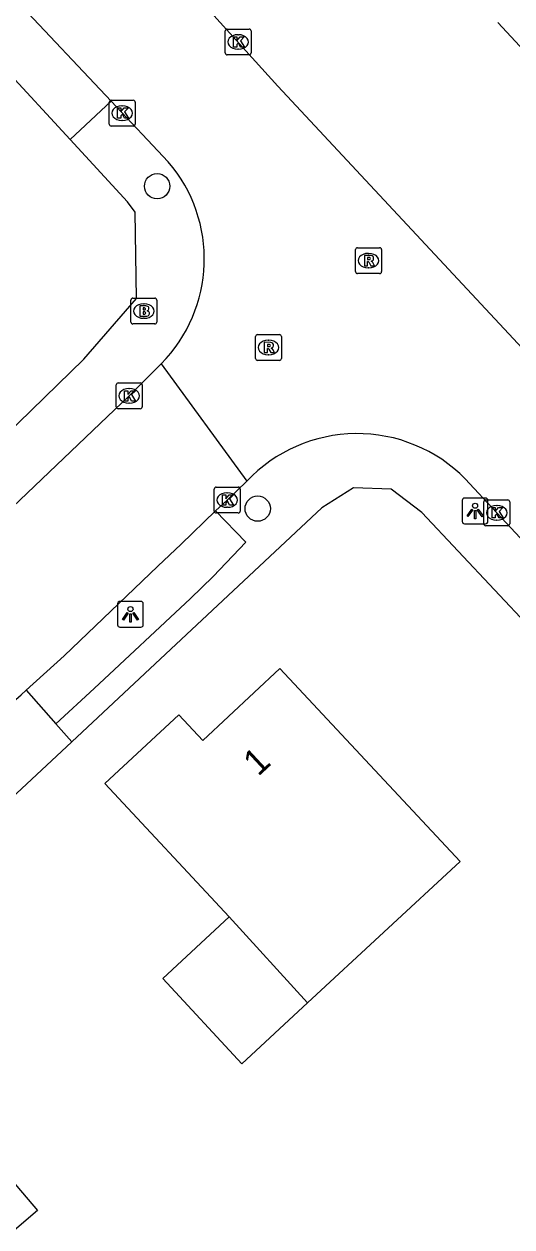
# Model space of a CAD drawing. Extents: x 162675 to 163482, y 379761 to 381227.
# Drawn here: x 163281.52 to 163300.37, y 380931.1 to 380977.63 of the extents above; entities that cross this region are included whole.
import ezdxf

# ---------------------------------------------------------------- set-up
doc = ezdxf.new("R2010")
doc.units = 0
for name, color, linetype in [('IMGEO_Berm_groen', 7, 'Continuous'), ('IMGEO_Boom', 7, 'Continuous'), ('IMGEO_Brandkraan', 7, 'Continuous'), ('IMGEO_Kolk', 7, 'Continuous'), ('IMGEO_Lichtpunt', 7, 'Continuous'), ('IMGEO_Pand', 7, 'Continuous'), ('IMGEO_Pand_nummerreeks', 7, 'Continuous'), ('IMGEO_Rijbaan_lokaal_gesloten', 7, 'Continuous'), ('IMGEO_Rioolput', 7, 'Continuous'), ('IMGEO_Voetpad_open', 7, 'Continuous')]:
    doc.layers.add(name, color=color, linetype=linetype)

msp = doc.modelspace()

# ---------------------------------------------------------------- linework, layer by layer
at = {"layer": 'IMGEO_Berm_groen'}
for points in [[(163283.301, 380973.164), (163270.341, 380987.244), (163262.225, 380995.879)], [(163284.882, 380974.654), (163283.301, 380973.164)], [(163245.355, 380932.175), (163256.849, 380940.728), (163265.587, 380947.667), (163275.197, 380956.267), (163283.823, 380964.675), (163285.861, 380967.011), (163285.811, 380970.355), (163285.512, 380970.762), (163283.301, 380973.164)], [(163317.332, 380927.055), (163320.579, 380929.984), (163321.057, 380930.657), (163321.299, 380931.564), (163321.184, 380932.515), (163320.761, 380933.306), (163296.884, 380958.739), (163295.699, 380959.641), (163294.252, 380959.688), (163293.024, 380958.913), (163283.361, 380949.868)], [(163288.921, 380958.797), (163290.086, 380957.585), (163288.827, 380956.259), (163287.951, 380955.412), (163284.229, 380951.924), (163282.745, 380950.566)]]:
    msp.add_lwpolyline(points, dxfattribs=at)
at = {"layer": 'IMGEO_Boom'}
for centre in [(163286.66, 380971.36), (163290.547, 380958.887)]:
    msp.add_circle(centre, 0.489, dxfattribs=at)
at = {"layer": 'IMGEO_Brandkraan'}
for p, q in [((163285.644, 380966.104), (163285.644, 380966.956)), ((163285.719, 380967.03), (163286.571, 380967.03)), ((163286.132, 380966.81), (163286.157, 380966.81)), ((163286.645, 380966.956), (163286.645, 380966.104)), ((163286.155, 380966.25), (163286.13, 380966.25)), ((163286.571, 380966.03), (163285.719, 380966.03))]:
    msp.add_line(p, q, dxfattribs=at)
for points in [[(163285.644, 380966.104), (163285.644, 380966.956)], [(163285.719, 380967.03), (163286.571, 380967.03)], [(163285.992, 380966.73), (163285.992, 380966.33), (163286.205, 380966.33)], [(163286.223, 380966.73), (163285.992, 380966.73)], [(163286.171, 380966.649), (163286.117, 380966.649), (163286.117, 380966.573)], [(163286.645, 380966.956), (163286.645, 380966.104)], [(163286.117, 380966.573), (163286.17, 380966.573)], [(163286.179, 380966.497), (163286.117, 380966.497), (163286.117, 380966.416)], [(163286.117, 380966.416), (163286.179, 380966.416)], [(163286.571, 380966.03), (163285.719, 380966.03)]]:
    msp.add_lwpolyline(points, dxfattribs=at)
for centre, radius, start, end in [((163285.721, 380966.954), 0.0765, 91.552, 178.448), ((163285.721, 380966.954), 0.0765, 91.552, 178.448), ((163286.172, 380966.611), 0.0379, 267.8285, 90.9355), ((163286.227, 380966.585), 0.145, 59.4692, 91.5367), ((163286.252, 380966.632), 0.0922, 285.5137, 58.1501), ((163286.569, 380966.954), 0.0765, 1.552, 88.448), ((163286.569, 380966.954), 0.0765, 1.552, 88.448), ((163286.18, 380966.456), 0.0404, 269.8759, 90.5077), ((163286.211, 380966.581), 0.251, 268.6676, 293.5347), ((163286.257, 380966.44), 0.105, 301.3115, 78.989), ((163285.721, 380966.106), 0.0765, 181.552, 268.448), ((163285.721, 380966.106), 0.0765, 181.552, 268.448), ((163286.569, 380966.106), 0.0765, 271.552, 358.448), ((163286.569, 380966.106), 0.0765, 271.552, 358.448)]:
    msp.add_arc(centre, radius, start, end, dxfattribs=at)
for centre, major_axis, ratio, start_param, end_param in [((163286.131, 380966.53), (-0.387, 0.002), 0.722429, 4.712389, 7.853982), ((163286.156, 380966.53), (-0.39, 0.002), 0.717154, 1.570796, 4.712389)]:
    msp.add_ellipse(centre, major_axis=major_axis, ratio=ratio, start_param=start_param, end_param=end_param, dxfattribs=at)
at = {"layer": 'IMGEO_Kolk'}
for p, q in [((163289.291, 380976.516), (163289.291, 380977.368)), ((163289.366, 380977.442), (163290.218, 380977.442)), ((163290.292, 380977.368), (163290.292, 380976.516)), ((163289.779, 380977.222), (163289.804, 380977.222)), ((163290.218, 380976.442), (163289.366, 380976.442)), ((163289.802, 380976.662), (163289.777, 380976.662)), ((163284.811, 380973.763), (163284.811, 380974.615)), ((163284.886, 380974.689), (163285.738, 380974.689)), ((163285.812, 380974.615), (163285.812, 380973.763)), ((163285.299, 380974.469), (163285.324, 380974.469)), ((163285.738, 380973.689), (163284.886, 380973.689)), ((163285.322, 380973.909), (163285.297, 380973.909)), ((163285.083, 380962.824), (163285.083, 380963.676)), ((163285.158, 380963.75), (163286.01, 380963.75)), ((163285.571, 380963.53), (163285.596, 380963.53)), ((163286.084, 380963.676), (163286.084, 380962.824)), ((163285.594, 380962.97), (163285.569, 380962.97)), ((163286.01, 380962.75), (163285.158, 380962.75)), ((163288.945, 380959.718), (163289.797, 380959.718)), ((163288.87, 380958.792), (163288.87, 380959.644)), ((163289.358, 380959.498), (163289.383, 380959.498)), ((163289.871, 380959.644), (163289.871, 380958.792)), ((163299.359, 380959.226), (163300.211, 380959.226)), ((163289.381, 380958.938), (163289.356, 380958.938)), ((163299.284, 380958.3), (163299.284, 380959.152)), ((163299.772, 380959.006), (163299.797, 380959.006)), ((163300.285, 380959.152), (163300.285, 380958.3)), ((163289.797, 380958.718), (163288.945, 380958.718)), ((163299.795, 380958.446), (163299.77, 380958.446)), ((163300.211, 380958.226), (163299.359, 380958.226))]:
    msp.add_line(p, q, dxfattribs=at)
for points in [[(163289.291, 380976.516), (163289.291, 380977.368)], [(163289.366, 380977.442), (163290.218, 380977.442)], [(163290.292, 380977.368), (163290.292, 380976.516)], [(163289.612, 380977.142), (163289.735, 380977.142), (163289.735, 380976.991), (163289.865, 380977.142), (163290.029, 380977.142), (163289.883, 380976.991), (163290.036, 380976.742), (163289.884, 380976.742), (163289.799, 380976.906), (163289.735, 380976.839), (163289.735, 380976.742), (163289.612, 380976.742), (163289.612, 380977.142)], [(163290.218, 380976.442), (163289.366, 380976.442)], [(163284.811, 380973.763), (163284.811, 380974.615)], [(163284.886, 380974.689), (163285.738, 380974.689)], [(163285.812, 380974.615), (163285.812, 380973.763)], [(163285.132, 380974.389), (163285.255, 380974.389), (163285.255, 380974.238), (163285.385, 380974.389), (163285.549, 380974.389), (163285.403, 380974.238), (163285.556, 380973.989), (163285.404, 380973.989), (163285.319, 380974.153), (163285.255, 380974.086), (163285.255, 380973.989), (163285.132, 380973.989), (163285.132, 380974.389)], [(163285.738, 380973.689), (163284.886, 380973.689)], [(163285.083, 380962.824), (163285.083, 380963.676)], [(163285.158, 380963.75), (163286.01, 380963.75)], [(163285.404, 380963.45), (163285.527, 380963.45), (163285.527, 380963.299), (163285.657, 380963.45), (163285.821, 380963.45), (163285.675, 380963.299), (163285.828, 380963.05), (163285.676, 380963.05), (163285.591, 380963.214), (163285.527, 380963.147), (163285.527, 380963.05), (163285.404, 380963.05), (163285.404, 380963.45)], [(163286.084, 380963.676), (163286.084, 380962.824)], [(163286.01, 380962.75), (163285.158, 380962.75)], [(163288.945, 380959.718), (163289.797, 380959.718)], [(163288.87, 380958.792), (163288.87, 380959.644)], [(163289.191, 380959.418), (163289.314, 380959.418), (163289.314, 380959.267), (163289.444, 380959.418), (163289.608, 380959.418), (163289.462, 380959.267), (163289.615, 380959.018), (163289.463, 380959.018), (163289.378, 380959.182), (163289.314, 380959.115), (163289.314, 380959.018), (163289.191, 380959.018), (163289.191, 380959.418)], [(163289.871, 380959.644), (163289.871, 380958.792)], [(163299.359, 380959.226), (163300.211, 380959.226)], [(163299.284, 380958.3), (163299.284, 380959.152)], [(163299.605, 380958.926), (163299.728, 380958.926), (163299.728, 380958.775), (163299.858, 380958.926), (163300.022, 380958.926), (163299.876, 380958.775), (163300.029, 380958.526), (163299.877, 380958.526), (163299.792, 380958.69), (163299.728, 380958.623), (163299.728, 380958.526), (163299.605, 380958.526), (163299.605, 380958.926)], [(163300.285, 380959.152), (163300.285, 380958.3)], [(163289.797, 380958.718), (163288.945, 380958.718)], [(163300.211, 380958.226), (163299.359, 380958.226)]]:
    msp.add_lwpolyline(points, dxfattribs=at)
for centre, start, end in [((163289.368, 380977.366), 91.552, 178.448), ((163289.368, 380977.366), 91.552, 178.448), ((163290.216, 380977.366), 1.552, 88.448), ((163290.216, 380977.366), 1.552, 88.448), ((163289.368, 380976.518), 181.552, 268.448), ((163289.368, 380976.518), 181.552, 268.448), ((163290.216, 380976.518), 271.552, 358.448), ((163290.216, 380976.518), 271.552, 358.448), ((163284.888, 380974.613), 91.552, 178.448), ((163284.888, 380974.613), 91.552, 178.448), ((163285.736, 380974.613), 1.552, 88.448), ((163285.736, 380974.613), 1.552, 88.448), ((163284.888, 380973.765), 181.552, 268.448), ((163284.888, 380973.765), 181.552, 268.448), ((163285.736, 380973.765), 271.552, 358.448), ((163285.736, 380973.765), 271.552, 358.448), ((163285.16, 380963.674), 91.552, 178.448), ((163285.16, 380963.674), 91.552, 178.448), ((163286.008, 380963.674), 1.552, 88.448), ((163286.008, 380963.674), 1.552, 88.448), ((163285.16, 380962.826), 181.552, 268.448), ((163285.16, 380962.826), 181.552, 268.448), ((163286.008, 380962.826), 271.552, 358.448), ((163286.008, 380962.826), 271.552, 358.448), ((163288.947, 380959.642), 91.552, 178.448), ((163288.947, 380959.642), 91.552, 178.448), ((163289.795, 380959.642), 1.552, 88.448), ((163289.795, 380959.642), 1.552, 88.448), ((163299.361, 380959.15), 91.552, 178.448), ((163299.361, 380959.15), 91.552, 178.448), ((163300.209, 380959.15), 1.552, 88.448), ((163300.209, 380959.15), 1.552, 88.448), ((163288.947, 380958.794), 181.552, 268.448), ((163288.947, 380958.794), 181.552, 268.448), ((163289.795, 380958.794), 271.552, 358.448), ((163289.795, 380958.794), 271.552, 358.448), ((163299.361, 380958.302), 181.552, 268.448), ((163299.361, 380958.302), 181.552, 268.448), ((163300.209, 380958.302), 271.552, 358.448), ((163300.209, 380958.302), 271.552, 358.448)]:
    msp.add_arc(centre, 0.0765, start, end, dxfattribs=at)
for centre, major_axis, ratio, start_param, end_param in [((163289.778, 380976.942), (-0.387, 0.002), 0.722429, 4.712389, 7.853982), ((163289.803, 380976.942), (-0.39, 0.002), 0.717154, 1.570796, 4.712389), ((163285.298, 380974.189), (-0.387, 0.002), 0.722429, 4.712389, 7.853982), ((163285.323, 380974.189), (-0.39, 0.002), 0.717154, 1.570796, 4.712389), ((163285.57, 380963.25), (-0.387, 0.002), 0.722429, 4.712389, 7.853982), ((163285.595, 380963.25), (-0.39, 0.002), 0.717154, 1.570796, 4.712389), ((163289.357, 380959.218), (-0.387, 0.002), 0.722429, 4.712389, 7.853982), ((163289.382, 380959.218), (-0.39, 0.002), 0.717154, 1.570796, 4.712389), ((163299.771, 380958.726), (-0.387, 0.002), 0.722429, 4.712389, 7.853982), ((163299.796, 380958.726), (-0.39, 0.002), 0.717154, 1.570796, 4.712389)]:
    msp.add_ellipse(centre, major_axis=major_axis, ratio=ratio, start_param=start_param, end_param=end_param, dxfattribs=at)
at = {"layer": 'IMGEO_Lichtpunt'}
for p, q in [((163298.449, 380959.202), (163298.449, 380958.395)), ((163298.449, 380959.202), (163298.449, 380958.395)), ((163299.351, 380959.297), (163298.543, 380959.297)), ((163299.351, 380959.297), (163298.543, 380959.297)), ((163299.445, 380958.395), (163299.445, 380959.202)), ((163299.445, 380958.395), (163299.445, 380959.202)), ((163298.543, 380958.301), (163299.351, 380958.301)), ((163298.543, 380958.301), (163299.351, 380958.301)), ((163285.13, 380955.202), (163285.13, 380954.395)), ((163285.13, 380955.202), (163285.13, 380954.395)), ((163286.032, 380955.297), (163285.224, 380955.297)), ((163286.032, 380955.297), (163285.224, 380955.297)), ((163286.126, 380954.395), (163286.126, 380955.202)), ((163286.126, 380954.395), (163286.126, 380955.202)), ((163285.224, 380954.301), (163286.032, 380954.301)), ((163285.224, 380954.301), (163286.032, 380954.301))]:
    msp.add_line(p, q, dxfattribs=at)
for points in [[(163298.823, 380958.866), (163298.862, 380958.838), (163298.674, 380958.576), (163298.636, 380958.603), (163298.823, 380958.866)], [(163298.925, 380958.818), (163298.972, 380958.818), (163298.972, 380958.496), (163298.925, 380958.496), (163298.925, 380958.818)], [(163299.035, 380958.838), (163299.073, 380958.865), (163299.26, 380958.603), (163299.221, 380958.575), (163299.035, 380958.838)], [(163285.504, 380954.866), (163285.543, 380954.838), (163285.355, 380954.576), (163285.317, 380954.603), (163285.504, 380954.866)], [(163285.606, 380954.818), (163285.653, 380954.818), (163285.653, 380954.496), (163285.606, 380954.496), (163285.606, 380954.818)], [(163285.716, 380954.838), (163285.754, 380954.865), (163285.941, 380954.603), (163285.902, 380954.575), (163285.716, 380954.838)]]:
    msp.add_lwpolyline(points, dxfattribs=at)
for centre in [(163298.948, 380959), (163285.629, 380955)]:
    msp.add_circle(centre, 0.0994, dxfattribs=at)
for centre, start, end in [((163298.543, 380959.202), 90, 180), ((163298.543, 380959.202), 90, 180), ((163299.351, 380959.202), 0, 90), ((163299.351, 380959.202), 0, 90), ((163298.543, 380958.395), 180, 270), ((163298.543, 380958.395), 180, 270), ((163299.351, 380958.395), 270, 0), ((163299.351, 380958.395), 270, 360), ((163285.224, 380955.202), 90, 180), ((163285.224, 380955.202), 90, 180), ((163286.032, 380955.202), 0, 90), ((163286.032, 380955.202), 0, 90), ((163285.224, 380954.395), 180, 270), ((163285.224, 380954.395), 180, 270), ((163286.032, 380954.395), 270, 0), ((163286.032, 380954.395), 270, 360)]:
    msp.add_arc(centre, 0.0946, start, end, dxfattribs=at)
at = {"layer": 'IMGEO_Pand'}
for points in [[(163299.824, 380977.698), (163303.91, 380973.295)], [(163292.474, 380939.76), (163298.376, 380945.238), (163291.404, 380952.706), (163288.421, 380949.921), (163287.494, 380950.905), (163284.644, 380948.251), (163289.446, 380943.092)], [(163289.446, 380943.092), (163286.877, 380940.71), (163289.935, 380937.403), (163292.474, 380939.76)], [(163289.446, 380943.092), (163292.474, 380939.76)], [(163272.637, 380935.682), (163276.199, 380938.643), (163276.806, 380937.922), (163277.935, 380938.883), (163280.268, 380936.141), (163279.118, 380935.162), (163282.041, 380931.727), (163278.606, 380928.803), (163279.89, 380927.294), (163280.071, 380927.082), (163274.67, 380922.486), (163270.866, 380926.955), (163269.468, 380928.597), (163272.133, 380930.865), (163270.614, 380932.649), (163273.28, 380934.918), (163272.637, 380935.682)]]:
    msp.add_lwpolyline(points, dxfattribs=at)
at = {"layer": 'IMGEO_Rijbaan_lokaal_gesloten'}
for points in [[(163262.994, 380997.873), (163284.882, 380974.654)], [(163308.847, 380956.416), (163303.455, 380962.21), (163291.33, 380975.235), (163272.753, 380995.764)], [(163284.882, 380974.654), (163287.093, 380972.307)], [(163286.815, 380964.484), (163285.584, 380963.25), (163280.503, 380958.42)], [(163286.815, 380964.484), (163290.124, 380959.948)], [(163288.921, 380958.797), (163289.371, 380959.218), (163290.124, 380959.948)], [(163298.568, 380960.041), (163299.785, 380958.726), (163311.732, 380945.919), (163320.596, 380936.397), (163322.059, 380934.813)], [(163281.602, 380951.861), (163283.071, 380953.186), (163286.688, 380956.667), (163287.589, 380957.512), (163288.921, 380958.797)]]:
    msp.add_lwpolyline(points, dxfattribs=at)
for centre, radius, start, end in [((163282.7, 380968.547), 5.782, 315.3653, 40.5643), ((163294.391, 380955.922), 5.867, 44.5995, 136.6625), ((162724.481, 381570.415), 832.462, 311.710307, 312.008798)]:
    msp.add_arc(centre, radius, start, end, dxfattribs=at)
at = {"layer": 'IMGEO_Rioolput'}
for p, q in [((163294.407, 380968.981), (163295.259, 380968.981)), ((163294.332, 380968.055), (163294.332, 380968.907)), ((163294.82, 380968.761), (163294.845, 380968.761)), ((163295.333, 380968.907), (163295.333, 380968.055)), ((163294.843, 380968.201), (163294.818, 380968.201)), ((163295.259, 380967.981), (163294.407, 380967.981)), ((163290.463, 380964.695), (163290.463, 380965.547)), ((163290.538, 380965.621), (163291.39, 380965.621)), ((163290.951, 380965.401), (163290.976, 380965.401)), ((163291.464, 380965.547), (163291.464, 380964.695)), ((163290.974, 380964.841), (163290.949, 380964.841)), ((163291.39, 380964.621), (163290.538, 380964.621))]:
    msp.add_line(p, q, dxfattribs=at)
for points in [[(163294.407, 380968.981), (163295.259, 380968.981)], [(163294.332, 380968.055), (163294.332, 380968.907)], [(163294.921, 380968.679), (163294.669, 380968.681), (163294.669, 380968.281)], [(163294.847, 380968.6), (163294.793, 380968.6), (163294.793, 380968.519)], [(163294.793, 380968.519), (163294.845, 380968.519)], [(163295.333, 380968.907), (163295.333, 380968.055)], [(163294.669, 380968.281), (163294.793, 380968.281), (163294.793, 380968.443), (163294.804, 380968.443)], [(163294.851, 380968.414), (163294.922, 380968.281), (163295.062, 380968.281), (163294.997, 380968.407)], [(163295.259, 380967.981), (163294.407, 380967.981)], [(163290.463, 380964.695), (163290.463, 380965.547)], [(163290.538, 380965.621), (163291.39, 380965.621)], [(163291.052, 380965.319), (163290.8, 380965.321), (163290.8, 380964.921)], [(163290.978, 380965.24), (163290.924, 380965.24), (163290.924, 380965.159)], [(163291.464, 380965.547), (163291.464, 380964.695)], [(163290.8, 380964.921), (163290.924, 380964.921), (163290.924, 380965.083), (163290.935, 380965.083)], [(163290.924, 380965.159), (163290.976, 380965.159)], [(163290.982, 380965.054), (163291.053, 380964.921), (163291.193, 380964.921), (163291.128, 380965.047)], [(163291.39, 380964.621), (163290.538, 380964.621)]]:
    msp.add_lwpolyline(points, dxfattribs=at)
for centre, radius, start, end in [((163294.409, 380968.905), 0.0765, 91.552, 178.448), ((163294.409, 380968.905), 0.0765, 91.552, 178.448), ((163295.257, 380968.905), 0.0765, 1.552, 88.448), ((163295.257, 380968.905), 0.0765, 1.552, 88.448), ((163294.829, 380968.708), 0.19, 274.7715, 282.9687), ((163294.853, 380968.504), 0.0964, 77.0061, 93.1865), ((163294.867, 380968.561), 0.0378, 276.6634, 79.6772), ((163294.92, 380968.569), 0.109, 350.3612, 89.416), ((163294.918, 380968.569), 0.112, 277.5842, 350.9817), ((163294.409, 380968.057), 0.0765, 181.552, 268.448), ((163294.409, 380968.057), 0.0765, 181.552, 268.448), ((163294.803, 380968.39), 0.0533, 26.0293, 88.6989), ((163294.902, 380968.354), 0.108, 29.5134, 73.7905), ((163295.257, 380968.057), 0.0765, 271.552, 358.448), ((163295.257, 380968.057), 0.0765, 271.552, 358.448), ((163290.54, 380965.545), 0.0765, 91.552, 178.448), ((163290.54, 380965.545), 0.0765, 91.552, 178.448), ((163290.984, 380965.144), 0.0964, 77.0061, 93.1865), ((163290.998, 380965.201), 0.0378, 276.6634, 79.6772), ((163291.051, 380965.209), 0.109, 350.3612, 89.416), ((163291.388, 380965.545), 0.0765, 1.552, 88.448), ((163291.388, 380965.545), 0.0765, 1.552, 88.448), ((163290.934, 380965.03), 0.0533, 26.0293, 88.6989), ((163290.96, 380965.348), 0.19, 274.7715, 282.9687), ((163291.049, 380965.209), 0.112, 277.5842, 350.9817), ((163291.033, 380964.994), 0.108, 29.5134, 73.7905), ((163290.54, 380964.697), 0.0765, 181.552, 268.448), ((163290.54, 380964.697), 0.0765, 181.552, 268.448), ((163291.388, 380964.697), 0.0765, 271.552, 358.448), ((163291.388, 380964.697), 0.0765, 271.552, 358.448)]:
    msp.add_arc(centre, radius, start, end, dxfattribs=at)
for centre, major_axis, ratio, start_param, end_param in [((163294.819, 380968.481), (-0.387, 0.002), 0.722429, 4.712389, 7.853982), ((163294.844, 380968.481), (-0.39, 0.002), 0.717154, 1.570796, 4.712389), ((163290.95, 380965.121), (-0.387, 0.002), 0.722429, 4.712389, 7.853982), ((163290.975, 380965.121), (-0.39, 0.002), 0.717154, 1.570796, 4.712389)]:
    msp.add_ellipse(centre, major_axis=major_axis, ratio=ratio, start_param=start_param, end_param=end_param, dxfattribs=at)
at = {"layer": 'IMGEO_Voetpad_open'}
for points in [[(163281.602, 380951.861), (163282.745, 380950.566)], [(163282.745, 380950.566), (163283.361, 380949.868)], [(163283.361, 380949.868), (163280.252, 380946.958)]]:
    msp.add_lwpolyline(points, dxfattribs=at)

# ---------------------------------------------------------------- texts
at = {"layer": 'IMGEO_Pand_nummerreeks'}
msp.add_text('1', height=1, rotation=42.8343, dxfattribs=at).set_placement((163290.565, 380948.504))

doc.saveas('drawing.dxf')
